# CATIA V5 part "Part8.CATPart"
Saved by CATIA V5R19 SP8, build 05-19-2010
Part number: Part8
Bounding box of the stored display mesh (mm): x 0 to 540, y -63 to 63, z -63 to 63
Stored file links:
  C:\Users\ThinkMotion\Desktop\EU_thinkMotion\iao\IAO_MMS_Groupe3\gdespas\projet_Thinkmotion_GDESPAS\projet Thinkmotion GDESPAS\Assemblage gdespas\Part8.CATPart
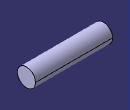
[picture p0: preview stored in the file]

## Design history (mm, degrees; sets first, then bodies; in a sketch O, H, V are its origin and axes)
Body1 (main body)
  Sketch1 on yz-plane, origin (0, 0, 0), H (0, 1, 0), V (0, 0, 1)
    circle A1 centre (0, 0) radius 63
    point P1 (-63, 0)
    radius A1 = 63
    coincidence: A1 P1, P1 H
  Pad1: profile Sketch1, direction (1, 0, 0), length 540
